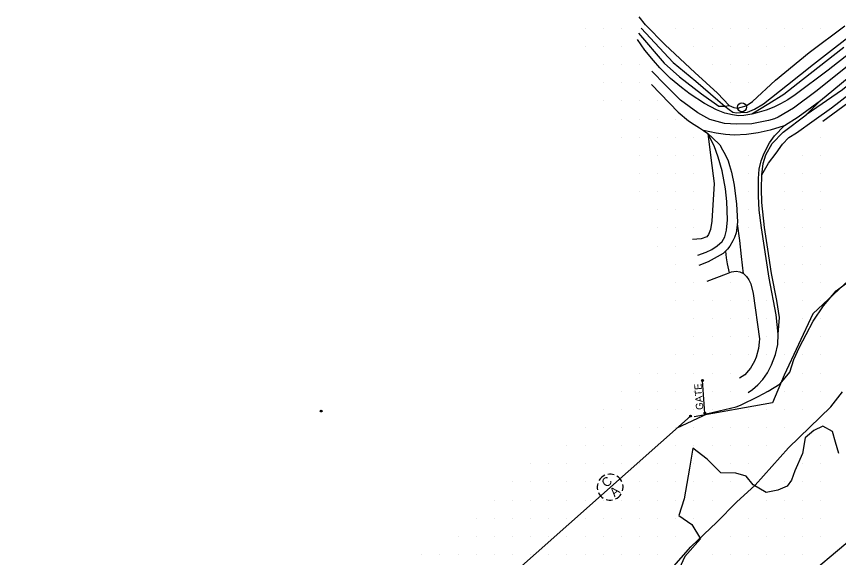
# Model space of a CAD drawing. Extents: x 1548934 to 1561348, y 809680 to 824075.
# Drawn here: x 1551186.6 to 1551639.7, y 810668.3 to 810966.6 of the extents above; entities that cross this region are included whole.
import ezdxf

# ---------------------------------------------------------------- set-up
doc = ezdxf.new("R2010")
doc.units = 0
for name, color, linetype in [('Default', 7, 'Continuous'), ('Exist DTM QL2 LIDAR Elevation Point', 7, 'Continuous'), ('Exist Other Culture Area Outline', 7, 'Continuous'), ('Exist Right of Way Control of Access CA Symbol CELL', 7, 'Continuous'), ('Exist Roads Soil', 7, 'Continuous'), ('Exist Utilities Other Pole CELL', 7, 'Continuous'), ('Exist Vegetation Woods Line', 7, 'Continuous'), ('P_RDY_Dimension_Text', 7, 'Continuous'), ('Pattern_1', 7, 'Continuous'), ('PH Exist DTM Breakline', 7, 'Continuous'), ('z - Construction', 7, 'Continuous')]:
    doc.layers.add(name, color=color, linetype=linetype)

# ---------------------------------------------------------------- blocks, each defined once
blk = doc.blocks.new('SurveyPointCell')
at = {"layer": 'Default'}
for p, q in [((-0.5, 0), (0.5, 0)), ((0, -0.5), (0, 0.5))]:
    blk.add_line(p, q, dxfattribs=at)
blk.add_circle((0, 0), 0.5, dxfattribs=at)

msp = doc.modelspace()

# ---------------------------------------------------------------- linework, layer by layer
at = {"layer": 'Exist DTM QL2 LIDAR Elevation Point'}
for p, q in [((1551499.98, 810960.01), (1551499.98, 810960.01)), ((1551509.98, 810960.01), (1551509.98, 810960.01)), ((1551519.98, 810960.01), (1551519.98, 810960.01)), ((1551549.98, 810960.01), (1551549.98, 810960.01)), ((1551559.98, 810960.01), (1551559.98, 810960.01)), ((1551569.98, 810960.01), (1551569.98, 810960.01)), ((1551579.99, 810960.01), (1551579.99, 810960.01)), ((1551589.99, 810960.01), (1551589.99, 810960.01)), ((1551599.99, 810960.01), (1551599.99, 810960.01)), ((1551609.99, 810960.01), (1551609.99, 810960.01)), ((1551619.99, 810960.01), (1551619.99, 810960.01)), ((1551629.99, 810960.01), (1551629.99, 810960.01)), ((1551499.98, 810950.01), (1551499.98, 810950.01)), ((1551509.98, 810950.01), (1551509.98, 810950.01)), ((1551519.98, 810950.01), (1551519.98, 810950.01)), ((1551559.98, 810950.01), (1551559.98, 810950.01)), ((1551569.98, 810950.01), (1551569.98, 810950.01)), ((1551579.99, 810950.01), (1551579.99, 810950.01)), ((1551589.99, 810950.01), (1551589.99, 810950.01)), ((1551599.99, 810950.01), (1551599.99, 810950.01)), ((1551609.99, 810950.01), (1551609.99, 810950.01)), ((1551509.98, 810940.01), (1551509.98, 810940.01)), ((1551519.98, 810940.01), (1551519.98, 810940.01)), ((1551529.98, 810940.01), (1551529.98, 810940.01)), ((1551569.98, 810940.01), (1551569.98, 810940.01)), ((1551579.99, 810940.01), (1551579.99, 810940.01)), ((1551589.99, 810940.01), (1551589.99, 810940.01)), ((1551599.99, 810940.01), (1551599.99, 810940.01)), ((1551509.98, 810930.01), (1551509.98, 810930.01)), ((1551519.98, 810930.01), (1551519.98, 810930.01)), ((1551529.98, 810930.01), (1551529.98, 810930.01)), ((1551579.99, 810930.01), (1551579.99, 810930.01)), ((1551589.99, 810930.01), (1551589.99, 810930.01)), ((1551509.98, 810920), (1551509.98, 810920)), ((1551519.98, 810920), (1551519.98, 810920)), ((1551529.98, 810920), (1551529.98, 810920)), ((1551539.98, 810920), (1551539.98, 810920)), ((1551519.98, 810910), (1551519.98, 810910)), ((1551529.98, 810910), (1551529.98, 810910)), ((1551539.98, 810910), (1551539.98, 810910)), ((1551549.98, 810910), (1551549.98, 810910)), ((1551519.98, 810900), (1551519.98, 810900)), ((1551529.98, 810900), (1551529.98, 810900)), ((1551539.98, 810900), (1551539.98, 810900)), ((1551549.98, 810900), (1551549.98, 810900)), ((1551559.98, 810900), (1551559.98, 810900)), ((1551629.99, 810900), (1551629.99, 810900)), ((1551529.98, 810890), (1551529.98, 810890)), ((1551539.98, 810890), (1551539.98, 810890)), ((1551549.98, 810890), (1551549.98, 810890)), ((1551559.98, 810890), (1551559.98, 810890)), ((1551589.99, 810890), (1551589.99, 810890)), ((1551619.99, 810890), (1551619.99, 810890)), ((1551629.99, 810890), (1551629.99, 810890)), ((1551529.98, 810880), (1551529.98, 810880)), ((1551539.98, 810880), (1551539.98, 810880)), ((1551549.98, 810880), (1551549.98, 810880)), ((1551559.98, 810880), (1551559.98, 810880)), ((1551589.99, 810880), (1551589.99, 810880)), ((1551609.99, 810880), (1551609.99, 810880)), ((1551619.99, 810880), (1551619.99, 810880)), ((1551629.99, 810880), (1551629.99, 810880)), ((1551529.98, 810870), (1551529.98, 810870)), ((1551539.98, 810870), (1551539.98, 810870)), ((1551549.98, 810870), (1551549.98, 810870)), ((1551559.98, 810870), (1551559.98, 810870)), ((1551589.99, 810870), (1551589.99, 810870)), ((1551609.99, 810870), (1551609.99, 810870)), ((1551619.99, 810870), (1551619.99, 810870)), ((1551629.99, 810870), (1551629.99, 810870)), ((1551539.98, 810860), (1551539.98, 810860)), ((1551549.98, 810860), (1551549.98, 810860)), ((1551559.98, 810860), (1551559.98, 810860)), ((1551589.99, 810860), (1551589.99, 810860)), ((1551609.99, 810860), (1551609.99, 810860)), ((1551619.99, 810860), (1551619.99, 810860)), ((1551629.99, 810860), (1551629.99, 810860)), ((1551539.98, 810850), (1551539.98, 810850)), ((1551549.98, 810850), (1551549.98, 810850)), ((1551559.98, 810850), (1551559.98, 810850)), ((1551589.99, 810850), (1551589.99, 810850)), ((1551609.99, 810850), (1551609.99, 810850)), ((1551619.99, 810850), (1551619.99, 810850)), ((1551629.99, 810850), (1551629.99, 810850)), ((1551539.98, 810840), (1551539.98, 810840)), ((1551549.98, 810840), (1551549.98, 810840)), ((1551609.99, 810840), (1551609.99, 810840)), ((1551619.99, 810840), (1551619.99, 810840)), ((1551629.99, 810840), (1551629.99, 810840)), ((1551549.98, 810830), (1551549.98, 810830)), ((1551609.99, 810830), (1551609.99, 810830)), ((1551619.99, 810830), (1551619.99, 810830)), ((1551629.99, 810830), (1551629.99, 810830)), ((1551549.98, 810820), (1551549.98, 810820)), ((1551559.98, 810820), (1551559.98, 810820)), ((1551579.99, 810820), (1551579.99, 810820)), ((1551609.99, 810820), (1551609.99, 810820)), ((1551619.99, 810820), (1551619.99, 810820)), ((1551629.99, 810820), (1551629.99, 810820)), ((1551549.98, 810810), (1551549.98, 810810)), ((1551559.98, 810810), (1551559.98, 810810)), ((1551569.98, 810810), (1551569.98, 810810)), ((1551579.99, 810810), (1551579.99, 810810)), ((1551589.99, 810810), (1551589.99, 810810)), ((1551599.99, 810810), (1551599.99, 810810)), ((1551619.99, 810810), (1551619.99, 810810)), ((1551629.99, 810810), (1551629.99, 810810)), ((1551559.98, 810799.99), (1551559.98, 810799.99)), ((1551569.98, 810799.99), (1551569.98, 810799.99)), ((1551579.99, 810799.99), (1551579.99, 810799.99)), ((1551589.99, 810799.99), (1551589.99, 810799.99)), ((1551599.99, 810799.99), (1551599.99, 810799.99)), ((1551619.99, 810799.99), (1551619.99, 810799.99)), ((1551629.99, 810799.99), (1551629.99, 810799.99)), ((1551559.98, 810789.99), (1551559.98, 810789.99)), ((1551569.98, 810789.99), (1551569.98, 810789.99)), ((1551579.99, 810789.99), (1551579.99, 810789.99)), ((1551589.99, 810789.99), (1551589.99, 810789.99)), ((1551599.99, 810789.99), (1551599.99, 810789.99)), ((1551619.99, 810789.99), (1551619.99, 810789.99)), ((1551629.99, 810789.99), (1551629.99, 810789.99)), ((1551549.98, 810779.99), (1551549.98, 810779.99)), ((1551559.98, 810779.99), (1551559.98, 810779.99)), ((1551569.98, 810779.99), (1551569.98, 810779.99)), ((1551579.99, 810779.99), (1551579.99, 810779.99)), ((1551589.99, 810779.99), (1551589.99, 810779.99)), ((1551599.99, 810779.99), (1551599.99, 810779.99)), ((1551609.99, 810779.99), (1551609.99, 810779.99)), ((1551619.99, 810779.99), (1551619.99, 810779.99)), ((1551629.99, 810779.99), (1551629.99, 810779.99)), ((1551529.98, 810769.99), (1551529.98, 810769.99)), ((1551539.98, 810769.99), (1551539.98, 810769.99)), ((1551549.98, 810769.99), (1551549.98, 810769.99)), ((1551559.98, 810769.99), (1551559.98, 810769.99)), ((1551569.98, 810769.99), (1551569.98, 810769.99)), ((1551579.99, 810769.99), (1551579.99, 810769.99)), ((1551609.99, 810769.99), (1551609.99, 810769.99)), ((1551619.99, 810769.99), (1551619.99, 810769.99)), ((1551629.99, 810769.99), (1551629.99, 810769.99)), ((1551519.98, 810759.99), (1551519.98, 810759.99)), ((1551529.98, 810759.99), (1551529.98, 810759.99)), ((1551539.98, 810759.99), (1551539.98, 810759.99)), ((1551549.98, 810759.99), (1551549.98, 810759.99)), ((1551559.98, 810759.99), (1551559.98, 810759.99)), ((1551569.98, 810759.99), (1551569.98, 810759.99)), ((1551579.99, 810759.99), (1551579.99, 810759.99)), ((1551599.99, 810759.99), (1551599.99, 810759.99)), ((1551609.99, 810759.99), (1551609.99, 810759.99)), ((1551619.99, 810759.99), (1551619.99, 810759.99)), ((1551629.99, 810759.99), (1551629.99, 810759.99)), ((1551509.98, 810749.99), (1551509.98, 810749.99)), ((1551519.98, 810749.99), (1551519.98, 810749.99)), ((1551529.98, 810749.99), (1551529.98, 810749.99)), ((1551539.98, 810749.99), (1551539.98, 810749.99)), ((1551549.98, 810749.99), (1551549.98, 810749.99)), ((1551559.98, 810749.99), (1551559.98, 810749.99)), ((1551569.98, 810749.99), (1551569.98, 810749.99)), ((1551579.99, 810749.99), (1551579.99, 810749.99)), ((1551589.99, 810749.99), (1551589.99, 810749.99)), ((1551599.99, 810749.99), (1551599.99, 810749.99)), ((1551609.99, 810749.99), (1551609.99, 810749.99)), ((1551619.99, 810749.99), (1551619.99, 810749.99)), ((1551499.98, 810739.99), (1551499.98, 810739.99)), ((1551509.98, 810739.99), (1551509.98, 810739.99)), ((1551519.98, 810739.99), (1551519.98, 810739.99)), ((1551529.98, 810739.99), (1551529.98, 810739.99)), ((1551539.98, 810739.99), (1551539.98, 810739.99)), ((1551549.98, 810739.99), (1551549.98, 810739.99)), ((1551559.98, 810739.99), (1551559.98, 810739.99)), ((1551569.98, 810739.99), (1551569.98, 810739.99)), ((1551579.99, 810739.99), (1551579.99, 810739.99)), ((1551589.99, 810739.99), (1551589.99, 810739.99)), ((1551599.99, 810739.99), (1551599.99, 810739.99)), ((1551609.99, 810739.99), (1551609.99, 810739.99)), ((1551489.98, 810729.99), (1551489.98, 810729.99)), ((1551499.98, 810729.99), (1551499.98, 810729.99)), ((1551509.98, 810729.99), (1551509.98, 810729.99)), ((1551519.98, 810729.99), (1551519.98, 810729.99)), ((1551529.98, 810729.99), (1551529.98, 810729.99)), ((1551539.98, 810729.99), (1551539.98, 810729.99)), ((1551549.98, 810729.99), (1551549.98, 810729.99)), ((1551559.98, 810729.99), (1551559.98, 810729.99)), ((1551569.98, 810729.99), (1551569.98, 810729.99)), ((1551579.99, 810729.99), (1551579.99, 810729.99)), ((1551589.99, 810729.99), (1551589.99, 810729.99)), ((1551599.99, 810729.99), (1551599.99, 810729.99)), ((1551629.99, 810729.99), (1551629.99, 810729.99)), ((1551469.98, 810719.99), (1551469.98, 810719.99)), ((1551479.98, 810719.99), (1551479.98, 810719.99)), ((1551489.98, 810719.99), (1551489.98, 810719.99)), ((1551499.98, 810719.99), (1551499.98, 810719.99)), ((1551509.98, 810719.99), (1551509.98, 810719.99)), ((1551519.98, 810719.99), (1551519.98, 810719.99)), ((1551529.98, 810719.99), (1551529.98, 810719.99)), ((1551539.98, 810719.99), (1551539.98, 810719.99)), ((1551549.98, 810719.99), (1551549.98, 810719.99)), ((1551559.98, 810719.99), (1551559.98, 810719.99)), ((1551569.98, 810719.99), (1551569.98, 810719.99)), ((1551579.99, 810719.99), (1551579.99, 810719.99)), ((1551589.99, 810719.99), (1551589.99, 810719.99)), ((1551619.99, 810719.99), (1551619.99, 810719.99)), ((1551629.99, 810719.99), (1551629.99, 810719.99)), ((1551459.98, 810709.99), (1551459.98, 810709.99)), ((1551469.98, 810709.99), (1551469.98, 810709.99)), ((1551479.98, 810709.99), (1551479.98, 810709.99)), ((1551489.98, 810709.99), (1551489.98, 810709.99)), ((1551499.98, 810709.99), (1551499.98, 810709.99)), ((1551509.98, 810709.99), (1551509.98, 810709.99)), ((1551519.98, 810709.99), (1551519.98, 810709.99)), ((1551529.98, 810709.99), (1551529.98, 810709.99)), ((1551539.98, 810709.99), (1551539.98, 810709.99)), ((1551549.98, 810709.99), (1551549.98, 810709.99)), ((1551559.98, 810709.99), (1551559.98, 810709.99)), ((1551569.98, 810709.99), (1551569.98, 810709.99)), ((1551579.99, 810709.99), (1551579.99, 810709.99)), ((1551609.99, 810709.99), (1551609.99, 810709.99)), ((1551619.99, 810709.99), (1551619.99, 810709.99)), ((1551629.99, 810709.99), (1551629.99, 810709.99)), ((1551449.98, 810699.99), (1551449.98, 810699.99)), ((1551459.98, 810699.99), (1551459.98, 810699.99)), ((1551469.98, 810699.99), (1551469.98, 810699.99)), ((1551479.98, 810699.99), (1551479.98, 810699.99)), ((1551489.98, 810699.99), (1551489.98, 810699.99)), ((1551499.98, 810699.99), (1551499.98, 810699.99)), ((1551509.98, 810699.99), (1551509.98, 810699.99)), ((1551519.98, 810699.99), (1551519.98, 810699.99)), ((1551529.98, 810699.99), (1551529.98, 810699.99)), ((1551539.98, 810699.99), (1551539.98, 810699.99)), ((1551549.98, 810699.99), (1551549.98, 810699.99)), ((1551559.98, 810699.99), (1551559.98, 810699.99)), ((1551569.98, 810699.99), (1551569.98, 810699.99)), ((1551599.99, 810699.99), (1551599.99, 810699.99)), ((1551609.99, 810699.99), (1551609.99, 810699.99)), ((1551619.99, 810699.99), (1551619.99, 810699.99)), ((1551629.99, 810699.99), (1551629.99, 810699.99)), ((1551439.97, 810689.99), (1551439.97, 810689.99)), ((1551449.98, 810689.99), (1551449.98, 810689.99)), ((1551459.98, 810689.99), (1551459.98, 810689.99)), ((1551469.98, 810689.99), (1551469.98, 810689.99)), ((1551479.98, 810689.99), (1551479.98, 810689.99)), ((1551489.98, 810689.99), (1551489.98, 810689.99)), ((1551499.98, 810689.99), (1551499.98, 810689.99)), ((1551509.98, 810689.99), (1551509.98, 810689.99)), ((1551519.98, 810689.99), (1551519.98, 810689.99)), ((1551529.98, 810689.99), (1551529.98, 810689.99)), ((1551539.98, 810689.99), (1551539.98, 810689.99)), ((1551549.98, 810689.99), (1551549.98, 810689.99)), ((1551559.98, 810689.99), (1551559.98, 810689.99)), ((1551589.99, 810689.99), (1551589.99, 810689.99)), ((1551599.99, 810689.99), (1551599.99, 810689.99)), ((1551609.99, 810689.99), (1551609.99, 810689.99)), ((1551619.99, 810689.99), (1551619.99, 810689.99)), ((1551629.99, 810689.99), (1551629.99, 810689.99)), ((1551429.97, 810679.99), (1551429.97, 810679.99)), ((1551439.97, 810679.99), (1551439.97, 810679.99)), ((1551449.98, 810679.99), (1551449.98, 810679.99)), ((1551459.98, 810679.99), (1551459.98, 810679.99)), ((1551469.98, 810679.99), (1551469.98, 810679.99)), ((1551479.98, 810679.99), (1551479.98, 810679.99)), ((1551489.98, 810679.99), (1551489.98, 810679.99)), ((1551499.98, 810679.99), (1551499.98, 810679.99)), ((1551509.98, 810679.99), (1551509.98, 810679.99)), ((1551519.98, 810679.99), (1551519.98, 810679.99)), ((1551529.98, 810679.99), (1551529.98, 810679.99)), ((1551539.98, 810679.99), (1551539.98, 810679.99)), ((1551549.98, 810679.99), (1551549.98, 810679.99)), ((1551579.99, 810679.99), (1551579.99, 810679.99)), ((1551589.99, 810679.99), (1551589.99, 810679.99)), ((1551599.99, 810679.99), (1551599.99, 810679.99)), ((1551609.99, 810679.99), (1551609.99, 810679.99)), ((1551619.99, 810679.99), (1551619.99, 810679.99)), ((1551629.99, 810679.99), (1551629.99, 810679.99)), ((1551409.97, 810669.98), (1551409.97, 810669.98)), ((1551419.97, 810669.98), (1551419.97, 810669.98)), ((1551429.97, 810669.98), (1551429.97, 810669.98)), ((1551439.97, 810669.98), (1551439.97, 810669.98)), ((1551449.98, 810669.98), (1551449.98, 810669.98)), ((1551459.98, 810669.98), (1551459.98, 810669.98)), ((1551469.98, 810669.98), (1551469.98, 810669.98)), ((1551479.98, 810669.98), (1551479.98, 810669.98)), ((1551489.98, 810669.98), (1551489.98, 810669.98)), ((1551499.98, 810669.98), (1551499.98, 810669.98)), ((1551509.98, 810669.98), (1551509.98, 810669.98)), ((1551519.98, 810669.98), (1551519.98, 810669.98)), ((1551529.98, 810669.98), (1551529.98, 810669.98)), ((1551539.98, 810669.98), (1551539.98, 810669.98)), ((1551569.98, 810669.98), (1551569.98, 810669.98)), ((1551579.99, 810669.98), (1551579.99, 810669.98)), ((1551589.99, 810669.98), (1551589.99, 810669.98)), ((1551599.99, 810669.98), (1551599.99, 810669.98)), ((1551609.99, 810669.98), (1551609.99, 810669.98)), ((1551619.99, 810669.98), (1551619.99, 810669.98))]:
    msp.add_line(p, q, dxfattribs=at)
at = {"layer": 'Exist Other Culture Area Outline'}
msp.add_line((1551631, 810908.82), (1551700.72, 810960.62), dxfattribs=at)
at = {"layer": 'Exist Right of Way Control of Access CA Symbol CELL'}
msp.add_line((1551513.79, 810707.16), (1551513.79, 810707.16), dxfattribs=at)
for start, end in [(113.9162, 149.5284), (71.5349, 100.1228), (25.1429, 58.3017), (163.3219, 191.9097), (343.3219, 11.9097), (205.1429, 238.3017), (293.9162, 329.5284), (251.5349, 280.1228)]:
    msp.add_arc((1551513.79, 810707.16), 7.14, start, end, dxfattribs=at)
at = {"layer": 'Exist Roads Soil'}
for points in [[(1551645.88, 810946.36), (1551633.92, 810937.07), (1551615.82, 810923.31), (1551611.75, 810920.67), (1551607.72, 810918.44), (1551603.96, 810916.54), (1551599.8, 810915), (1551595.86, 810913.82), (1551591.83, 810912.72), (1551587.49, 810912.02), (1551584.5, 810911.85), (1551581.19, 810912.29), (1551577.07, 810913.26), (1551572.48, 810915.13), (1551565.81, 810918.61), (1551557.94, 810923.76), (1551553.18, 810927.44), (1551547.04, 810932.34), (1551541.25, 810938.21), (1551537.65, 810942.28), (1551532.97, 810948.02), (1551528.82, 810953.89)], [(1551589.81, 810759.31), (1551592.33, 810761.02), (1551595.26, 810763.5), (1551598.01, 810766.53), (1551600.48, 810770.2), (1551602.83, 810774.56), (1551605.01, 810780.22), (1551606.22, 810785.77), (1551606.44, 810791.38), (1551605.36, 810802.14), (1551601.49, 810822.33), (1551597.16, 810850.16), (1551595.89, 810859.78), (1551595.54, 810867.57), (1551595.62, 810877.25), (1551596.03, 810882.47), (1551597.07, 810887.01), (1551598.64, 810891.33), (1551601.66, 810896.88), (1551604.33, 810900.79), (1551609.89, 810906.48), (1551617.35, 810911.24), (1551629.82, 810920.36), (1551648.6, 810935.94)], [(1551536.58, 810929.1), (1551551.32, 810913.92), (1551557.08, 810909.12), (1551560.18, 810907.02), (1551563.03, 810905.28), (1551565.31, 810903.75), (1551567.7, 810902.03), (1551570.31, 810899.7), (1551574.19, 810895.78), (1551575.68, 810893.07), (1551577.19, 810890.48), (1551578.81, 810887.08), (1551579.66, 810884.43), (1551580.62, 810880.81), (1551582.13, 810873.59), (1551583.48, 810863.21), (1551584.07, 810853.41), (1551583.64, 810850.05), (1551583.19, 810847.24), (1551582.33, 810844.8), (1551581.35, 810842.88), (1551579.85, 810840), (1551578.46, 810838.28), (1551577.24, 810837.07), (1551576.15, 810835.96), (1551567.91, 810831.33), (1551562.74, 810829.28)], [(1551567.32, 810820.68), (1551577.9, 810824.76), (1551580.76, 810825.79), (1551583.28, 810826.2), (1551585.21, 810825.85), (1551587.29, 810824.87), (1551588.89, 810823.33), (1551590.25, 810821.36), (1551591.34, 810819.14), (1551592.66, 810813.83), (1551596.05, 810788.9), (1551596.02, 810787.02), (1551595.49, 810783.62), (1551594.36, 810778.83), (1551593.32, 810776.61), (1551591.23, 810772.79), (1551590.13, 810771.4), (1551588.05, 810769.05), (1551585.11, 810767.25)]]:
    msp.add_lwpolyline(points, dxfattribs=at)
at = {"layer": 'Exist Utilities Other Pole CELL'}
msp.add_circle((1551586.44, 810916.55), 2.46, dxfattribs=at)
at = {"layer": 'Exist Vegetation Woods Line'}
for points in [[(1551612.77, 810770.56), (1551614.98, 810777.57), (1551618.17, 810784.31), (1551621.9, 810791.23), (1551625.63, 810798.61), (1551631.45, 810807.01), (1551638.36, 810815.33), (1551659.01, 810830.79)], [(1551583.19, 810751.42), (1551585.65, 810752.27), (1551595.43, 810757.14), (1551600.84, 810760.06), (1551607.51, 810764.18), (1551612.77, 810770.56)], [(1551550.76, 810739.77), (1551567.64, 810747.79), (1551583.19, 810751.42)], [(1551639.78, 810725.64), (1551637.95, 810731.88), (1551636.4, 810737.75), (1551631.08, 810740.81), (1551626.12, 810738.35), (1551621.22, 810734.39), (1551619.79, 810725.66), (1551615.58, 810716.13), (1551613.7, 810710.91), (1551611.44, 810707.69)], [(1551611.44, 810707.69), (1551606.25, 810705.44), (1551599.85, 810704.18), (1551592.59, 810708.38), (1551588.79, 810713.25), (1551583.16, 810714.92), (1551574.9, 810714.97), (1551567.23, 810722.61), (1551559.46, 810728.55), (1551557.63, 810717.67), (1551554.62, 810700.76), (1551551.64, 810691.55), (1551558.92, 810686.48), (1551563.54, 810678.6), (1551555.04, 810668.94), (1551545.76, 810648.88)]]:
    msp.add_lwpolyline(points, dxfattribs=at)
at = {"layer": 'P_RDY_Dimension_Text'}
for points in [[(1551760.85, 810852.38), (1551753.88, 810847.55), (1551716.43, 810885.61), (1551695.29, 810867.16), (1551642.57, 810818.58), (1551625.51, 810802.67), (1551609.65, 810768.78), (1551603.27, 810753.55)], [(1551603.27, 810753.55), (1551560.05, 810745.87)], [(1551558.11, 810746.33), (1551456.62, 810656.3), (1551333.17, 810546.96), (1551186.58, 810416.65)]]:
    msp.add_lwpolyline(points, dxfattribs=at)
at = {"layer": 'Pattern_1'}
msp.add_lwpolyline([(1551566.05, 810747.97), (1551564.72, 810765.95)], dxfattribs=at)
at = {"layer": 'PH Exist DTM Breakline'}
for points in [[(1551726.07, 810987.63), (1551714.72, 810983.85), (1551704.75, 810980.66), (1551697.9, 810977.6), (1551689.75, 810973.07), (1551679.24, 810966.2), (1551665.31, 810955.49), (1551646.45, 810940.69), (1551627.97, 810925.75), (1551614.84, 810916.02), (1551606.45, 810911.08), (1551604.44, 810910.12), (1551601.05, 810909.28), (1551591.96, 810907.48), (1551583.41, 810907.17), (1551576.77, 810907.65), (1551568.84, 810909.78), (1551562.19, 810913.41), (1551552.65, 810920.44), (1551544.29, 810928.79), (1551536.7, 810936.36)], [(1551756.6, 810893.45), (1551744.48, 810918.77), (1551737.77, 810938.57), (1551731.45, 810955.6), (1551727.45, 810965), (1551725.9, 810967.28), (1551723.52, 810969.49), (1551719.68, 810971.06), (1551716.03, 810972.06), (1551713.36, 810972.06), (1551709.28, 810971.65), (1551705.62, 810970.61), (1551696.74, 810966.37), (1551681.91, 810957.07), (1551664.96, 810944.51), (1551652.69, 810934.96), (1551641.8, 810926.1), (1551621.87, 810912.31)], [(1551579.49, 810917.53), (1551572.99, 810924.38), (1551560.42, 810935.62), (1551544.13, 810950.94), (1551533.33, 810961.94), (1551529.86, 810966.31)], [(1551529.37, 810957.46), (1551543.57, 810940.86), (1551551.99, 810933.33), (1551564.14, 810923.92), (1551573.63, 810917.18), (1551576.97, 810917.09), (1551579.49, 810917.53), (1551582.07, 810916.37), (1551584.09, 810916.01), (1551586.08, 810916.55), (1551588.77, 810917.33), (1551592.18, 810919.7), (1551604.95, 810931.53), (1551623.45, 810946.73), (1551643.13, 810961.35)], [(1551530.86, 810960.11), (1551548.63, 810941.29), (1551561.05, 810930.91), (1551573.07, 810920.47), (1551576.97, 810917.09), (1551579.36, 810915.24), (1551581.5, 810913.93), (1551583.54, 810913.5), (1551585.69, 810913.6), (1551589.45, 810913.91), (1551593.4, 810915.54), (1551598.28, 810918.34), (1551611.56, 810928.86), (1551625.86, 810940.3), (1551653.05, 810961.36)], [(1551642.56, 810949.47), (1551619.76, 810931.61), (1551609.56, 810923.61), (1551601.29, 810918.38), (1551591.83, 810912.72)], [(1551606.44, 810791.38), (1551607.14, 810800.63), (1551605.68, 810810.05), (1551602.67, 810824.99), (1551600.76, 810838.39), (1551598.95, 810850.22), (1551597.37, 810864.1), (1551597.14, 810871.55), (1551597.41, 810879.38), (1551598.2, 810885.49), (1551599.61, 810890.41), (1551603.08, 810896.52), (1551609.15, 810902.82), (1551621.87, 810912.31), (1551629.82, 810920.36)], [(1551597.41, 810879.38), (1551601.1, 810885.64), (1551605.27, 810891.15), (1551608.76, 810896.15), (1551612.33, 810899.9), (1551616.54, 810902.4), (1551626.31, 810909.4), (1551635.81, 810916.17), (1551645.58, 810923.81)], [(1551609.77, 810906.35), (1551602.01, 810903.94), (1551595.35, 810902.38), (1551588.9, 810901.44), (1551582.14, 810901.24), (1551577.46, 810901.51), (1551572.19, 810902.25), (1551565.25, 810903.78)], [(1551562.08, 810835.06), (1551566.67, 810836.64), (1551569.82, 810838.14), (1551572.79, 810840.14), (1551575.53, 810842.62), (1551577.09, 810845.06), (1551577.98, 810848.81), (1551578.52, 810854.41), (1551578.19, 810864.64), (1551577.44, 810871.56), (1551575.57, 810881.54), (1551573.3, 810888.99), (1551571.08, 810895.27), (1551567.7, 810902.03), (1551569.37, 810888.74), (1551571.06, 810874.55), (1551569.91, 810853.68), (1551569.04, 810849.23), (1551567.95, 810846.47), (1551567.01, 810845.09), (1551563.99, 810844.06), (1551559.19, 810843.68)], [(1551587.36, 810824.8), (1551586.27, 810834.34), (1551585.37, 810843.16), (1551583.93, 810852.33)], [(1551577.4, 810837.22), (1551577.82, 810833.5), (1551578.38, 810830.31), (1551579.43, 810825.31)], [(1551769.85, 810786.11), (1551769.26, 810785.46), (1551767.65, 810783.55), (1551764.3, 810780.15), (1551753.46, 810769.58), (1551733.44, 810752.86), (1551714.65, 810736.26), (1551695.61, 810720.17), (1551671.3, 810700.1), (1551647.22, 810678.75), (1551618.4, 810654.5)], [(1551612.18, 810728.73), (1551635.42, 810751.45), (1551641.84, 810759.75)], [(1551372.12, 810479.59), (1551389.99, 810495.3), (1551400.65, 810506.84), (1551411.53, 810518.15), (1551427.33, 810537.4), (1551448.81, 810559.67), (1551462.35, 810572.24), (1551473.5, 810585.36), (1551489.47, 810601.74), (1551503.6, 810613.99), (1551514.42, 810622.53), (1551526.76, 810635.05), (1551537.34, 810647.7), (1551543.65, 810657.61), (1551558.31, 810674.34), (1551572.56, 810687.89), (1551583.53, 810698.87), (1551593.75, 810708.19), (1551612.18, 810728.73)]]:
    msp.add_lwpolyline(points, dxfattribs=at)

# ---------------------------------------------------------------- block references
at = {"layer": 'Default'}
for p in [(1551564.72, 810765.95), (1551354.57, 810749.1), (1551566.05, 810747.97), (1551558.11, 810746.33)]:
    msp.add_blockref('SurveyPointCell', p, dxfattribs=at)

# ---------------------------------------------------------------- texts
at = {"layer": 'Exist Right of Way Control of Access CA Symbol CELL'}
for s, p in [('C', (1551511.77, 810706.61)), ('A', (1551516.28, 810701.45))]:
    msp.add_text(s, height=5, rotation=41.7223, dxfattribs=at).set_placement(p)
at = {"layer": 'z - Construction'}
msp.add_text('GATE', height=4.02, rotation=94.2239, dxfattribs=at).set_placement((1551565.2, 810749.86))

doc.saveas('drawing.dxf')
